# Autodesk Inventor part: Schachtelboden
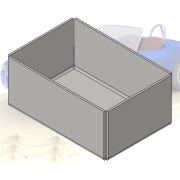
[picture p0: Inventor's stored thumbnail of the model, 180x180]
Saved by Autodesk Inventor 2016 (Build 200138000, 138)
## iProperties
Created: 2015-05
Part Number: Schachtelboden
Material: Generic
Document SubType Name: Sheet Metal
Designer: thomas
Density: 1 g/cm^3
Flat Pattern Width: 18.8048 cm
Flat Pattern Length: 22.8048 cm
Flat Pattern Area: 428.839 cm^2
Sheet Metal Rule: Standard_mm
Sheet Metal Width: 188,048 mm
Sheet Metal Length: 228,048 mm
Sheet Metal Area: 42883,882 mm^2
Appearance: Default
Author: thomas
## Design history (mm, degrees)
derived "Schachtel.ipt"
feature "Volumenkörper1::Schachtel.ipt" dims "d0" = 10
tag "Bezeichnung1"
node "Volumenkörper1"
feature "Definition1"
other parameters: "Thickness" = 2 (derived), "BendRadius" = 2 (= Thickness), "BendReliefWidth" = 2 (= Thickness), "BendReliefDepth" = 1 (= 0.5 x Thickness), "CornerReliefSize" = 8 (= 4 x Thickness), "SeamGap" = 0.01, "MinimumRemnant" = 4 (= 2 x Thickness), "TransitionRadius" = 2 (= BendRadius), "JacobiRadiusSize" = 2 (= BendRadius), "GapSize" = 1 (= 0.5 x Thickness), "BendRadius" = 2, "BendReliefDepth" = 1, "BendReliefWidth" = 2, "CornerReliefSize" = 8, "GapSize" = 1, "JacobiRadiusSize" = 2, "MinimumRemnant" = 4, "Thickness" = 2, "TransitionRadius" = 2
